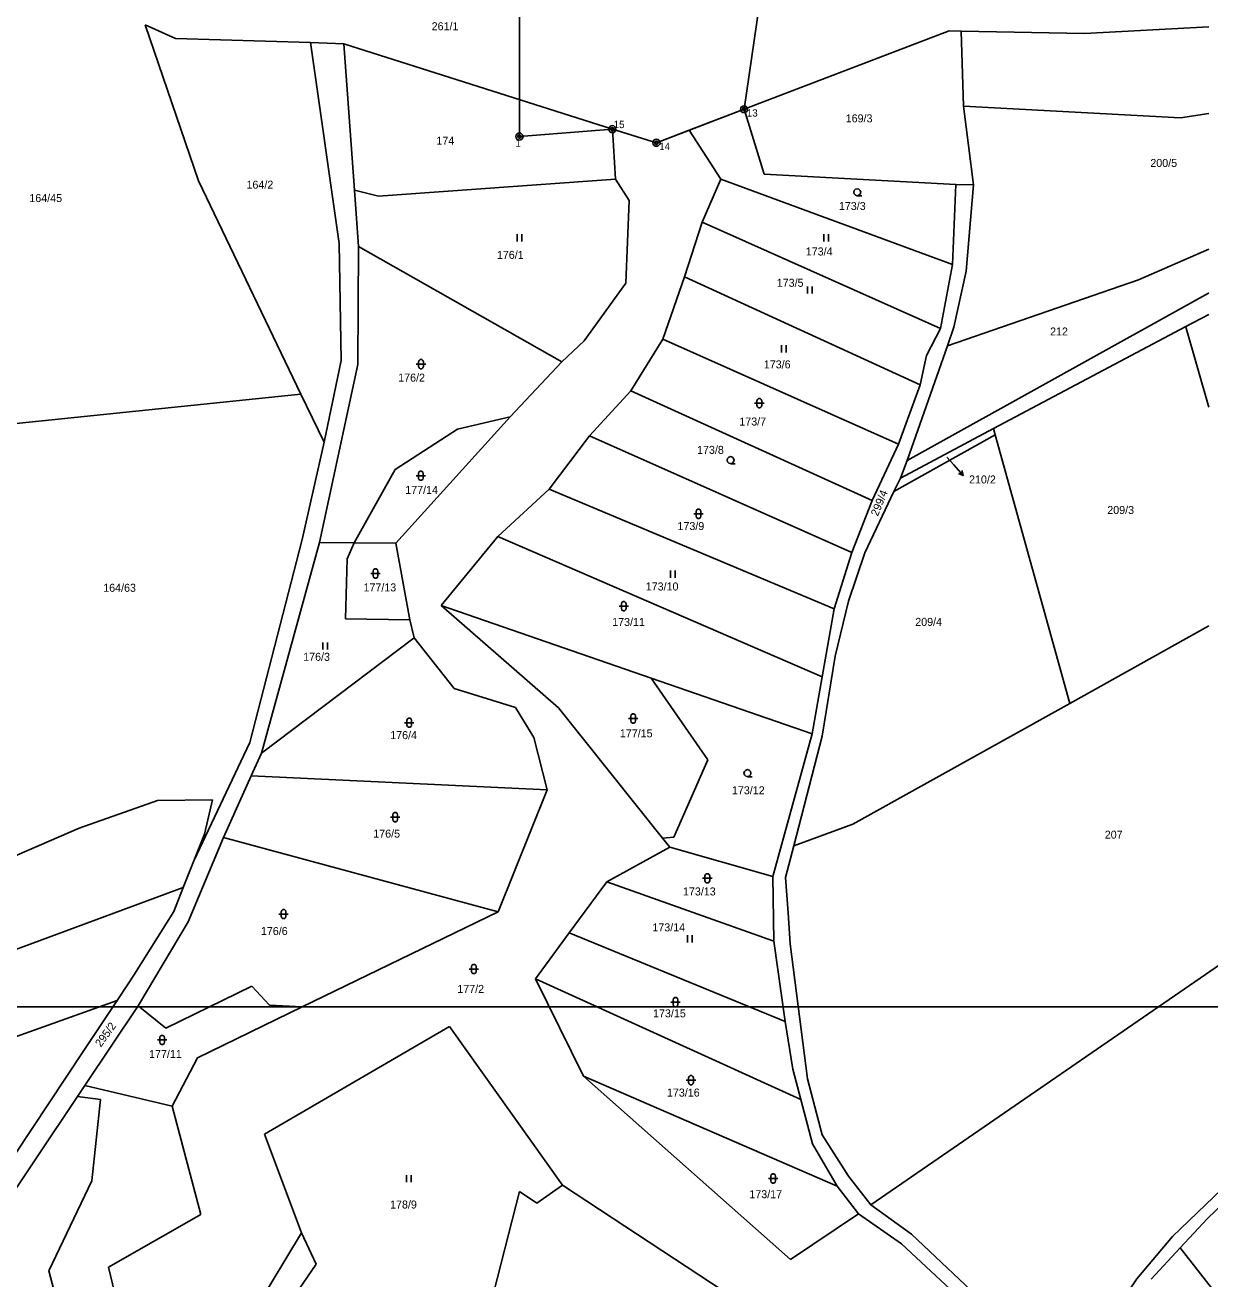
# Model space of a CAD drawing. Extents: x -779723 to -777378, y -1011169 to -1009297.
# Drawn here: x -779360.2 to -779108.5, y -1010745.7 to -1010479.3 of the extents above; entities that cross this region are included whole.
import ezdxf

# ---------------------------------------------------------------- set-up
doc = ezdxf.new("R2010")
doc.units = 0
for name, color, linetype in [('body', 7, 'Continuous'), ('cisla', 7, 'Continuous'), ('Default', 7, 'Continuous'), ('KN_HRANICE', 7, 'Continuous'), ('KN_KULTURY', 7, 'Continuous'), ('KN_PARCELY', 7, 'Continuous'), ('LEGENDA', 7, 'Continuous'), ('obvod_stavby', 7, 'Continuous')]:
    doc.layers.add(name, color=color, linetype=linetype)

# ---------------------------------------------------------------- blocks, each defined once
blk = doc.blocks.new('304')
at = {"layer": 'Default'}
blk.add_lwpolyline([(0, 0), (-0.38, 0.1), (-0.65, 0.37), (-0.75, 0.74), (-0.65, 1.11), (-0.38, 1.38), (-0.01, 1.48), (0.36, 1.38), (0.63, 1.11), (0.73, 0.73), (0.63, 0.35), (0.36, 0.08), (-0.02, -0.02), (0.98, -0.02)], dxfattribs=at)
blk = doc.blocks.new('306')
at = {"layer": 'Default'}
for p, q in [((-0.5, 1.5), (-0.5, 0)), ((0.5, 0), (0.5, 1.5))]:
    blk.add_line(p, q, dxfattribs=at)
blk = doc.blocks.new('316')
at = {"layer": 'Default'}
for points in [[(-1, 1), (0.27, 1), (1, 1)], [(-0.5, 1.5), (-0.4, 1.79), (-0.15, 1.97), (0.16, 1.97), (0.41, 1.79), (0.51, 1.5), (0.51, 0.5), (0.41, 0.21), (0.16, 0.03), (-0.15, 0.03), (-0.4, 0.21), (-0.5, 0.5), (-0.5, 1.5)]]:
    blk.add_lwpolyline(points, dxfattribs=at)
blk = doc.blocks.new('10292')
at = {"layer": 'Default'}
blk.add_line((0, 3), (0, 0), dxfattribs=at)
blk.add_lwpolyline([(-0.5, 2), (0, 3), (0.5, 2)], dxfattribs=at)

msp = doc.modelspace()

# ---------------------------------------------------------------- linework, layer by layer
at = {"layer": 'body'}
for p, q in [((-779207.48, -1010497.19), (-779207.48, -1010497.19)), ((-779235.46, -1010501.42), (-779235.46, -1010501.42)), ((-779255.21, -1010502.98), (-779255.21, -1010502.98)), ((-779226.1, -1010504.31), (-779226.1, -1010504.31))]:
    msp.add_line(p, q, dxfattribs=at)
for centre, radius in [((-779207.48, -1010497.19), 0.75), ((-779207.48, -1010497.19), 0.35), ((-779255.21, -1010502.98), 0.75), ((-779255.21, -1010502.98), 0.35), ((-779235.46, -1010501.42), 0.75), ((-779235.46, -1010501.42), 0.35), ((-779226.1, -1010504.31), 0.75), ((-779226.1, -1010504.31), 0.35)]:
    msp.add_circle(centre, radius, dxfattribs=at)
at = {"layer": 'KN_HRANICE'}
for p, q in [((-779334.72, -1010479.27), (-779323.42, -1010512.4)), ((-779334.72, -1010479.27), (-779328.3, -1010482.13)), ((-779207.48, -1010497.19), (-779163.89, -1010480.52)), ((-779163.89, -1010480.52), (-779161.4, -1010480.57)), ((-779161.4, -1010480.57), (-779160.87, -1010496.55)), ((-779161.4, -1010480.57), (-779135.21, -1010481.09)), ((-779135.21, -1010481.09), (-779108.78, -1010479.68)), ((-779299.61, -1010483.03), (-779328.3, -1010482.13)), ((-779292.52, -1010483.32), (-779299.61, -1010483.03)), ((-779299.61, -1010483.03), (-779293.5, -1010525.69)), ((-779292.52, -1010483.32), (-779290.27, -1010514.35)), ((-779292.52, -1010483.32), (-779235.46, -1010501.42)), ((-779219.15, -1010501.65), (-779207.48, -1010497.19)), ((-779207.48, -1010497.19), (-779203.19, -1010510.98)), ((-779160.87, -1010496.55), (-779158.79, -1010513.22)), ((-779160.87, -1010496.55), (-779114.77, -1010499.04)), ((-779114.77, -1010499.04), (-779108.78, -1010498.11)), ((-779235.46, -1010501.42), (-779234.79, -1010512.03)), ((-779235.46, -1010501.42), (-779226.1, -1010504.31)), ((-779226.1, -1010504.31), (-779219.15, -1010501.65)), ((-779212.41, -1010512.04), (-779219.15, -1010501.65)), ((-779301.63, -1010557.72), (-779323.42, -1010512.4)), ((-779234.79, -1010512.03), (-779285.14, -1010515.63)), ((-779234.79, -1010512.03), (-779231.92, -1010516.57)), ((-779212.41, -1010512.04), (-779216.37, -1010521.17)), ((-779212.41, -1010512.04), (-779163.24, -1010530.16)), ((-779203.19, -1010510.98), (-779162.49, -1010513.2)), ((-779162.49, -1010513.2), (-779163.24, -1010530.16)), ((-779162.49, -1010513.2), (-779158.79, -1010513.22)), ((-779158.79, -1010513.22), (-779160.29, -1010531.61)), ((-779290.27, -1010514.35), (-779285.14, -1010515.63)), ((-779290.27, -1010514.35), (-779289.37, -1010526.33)), ((-779231.92, -1010516.57), (-779232.59, -1010534.14)), ((-779216.37, -1010521.17), (-779220.16, -1010532.8)), ((-779216.37, -1010521.17), (-779165.77, -1010543.76)), ((-779293.5, -1010525.69), (-779293.08, -1010550.56)), ((-779289.37, -1010526.33), (-779289.53, -1010551.4)), ((-779246.22, -1010550.88), (-779289.37, -1010526.33)), ((-779123.71, -1010533.43), (-779108.78, -1010526.89)), ((-779163.24, -1010530.16), (-779165.77, -1010543.76)), ((-779160.29, -1010531.61), (-779162.91, -1010543.51)), ((-779232.59, -1010534.14), (-779241.43, -1010546.37)), ((-779220.16, -1010532.8), (-779224.72, -1010546.03)), ((-779220.16, -1010532.8), (-779170.1, -1010555.73)), ((-779164.3, -1010547.48), (-779123.71, -1010533.43)), ((-779108.83, -1010536.25), (-779172.82, -1010571.78)), ((-779108.78, -1010536.22), (-779108.83, -1010536.25)), ((-779113.68, -1010543.36), (-779108.78, -1010540.76)), ((-779165.77, -1010543.76), (-779168.72, -1010549.53)), ((-779162.91, -1010543.51), (-779164.3, -1010547.48)), ((-779154.51, -1010565.04), (-779113.68, -1010543.36)), ((-779113.58, -1010543.69), (-779113.68, -1010543.36)), ((-779108.78, -1010560.46), (-779113.58, -1010543.69)), ((-779246.22, -1010550.88), (-779241.43, -1010546.37)), ((-779224.72, -1010546.03), (-779231.57, -1010557.02)), ((-779224.72, -1010546.03), (-779174.68, -1010568.37)), ((-779164.3, -1010547.48), (-779172.82, -1010571.78)), ((-779293.08, -1010550.56), (-779296.69, -1010567.88)), ((-779168.72, -1010549.53), (-779170.1, -1010555.73)), ((-779289.53, -1010551.4), (-779297.68, -1010589.2)), ((-779257.2, -1010562.56), (-779246.22, -1010550.88)), ((-779170.1, -1010555.73), (-779174.68, -1010568.37)), ((-779389.01, -1010566.7), (-779301.63, -1010557.72)), ((-779296.69, -1010567.88), (-779301.63, -1010557.72)), ((-779231.57, -1010557.02), (-779240.34, -1010566.54)), ((-779231.57, -1010557.02), (-779180.29, -1010580.29)), ((-779281.44, -1010589.38), (-779257.2, -1010562.56)), ((-779268.35, -1010565.14), (-779257.2, -1010562.56)), ((-779281.62, -1010573.71), (-779268.35, -1010565.14)), ((-779240.34, -1010566.54), (-779248.92, -1010577.89)), ((-779240.34, -1010566.54), (-779184.61, -1010591.38)), ((-779154.14, -1010566.37), (-779175.66, -1010578.41)), ((-779174.28, -1010575.54), (-779154.51, -1010565.04)), ((-779154.14, -1010566.37), (-779154.51, -1010565.04)), ((-779138.26, -1010623.45), (-779154.14, -1010566.37)), ((-779296.69, -1010567.88), (-779301.39, -1010588.58)), ((-779174.68, -1010568.37), (-779180.29, -1010580.29)), ((-779172.82, -1010571.78), (-779174.28, -1010575.54)), ((-779290.32, -1010589.28), (-779281.62, -1010573.71)), ((-779174.28, -1010575.54), (-779175.66, -1010578.41)), ((-779248.92, -1010577.89), (-779259.78, -1010587.95)), ((-779248.92, -1010577.89), (-779188.38, -1010603.3)), ((-779175.66, -1010578.41), (-779181.87, -1010591.44)), ((-779180.29, -1010580.29), (-779184.61, -1010591.38)), ((-779301.39, -1010588.58), (-779312.45, -1010631.73)), ((-779297.68, -1010589.2), (-779309.99, -1010633.95)), ((-779297.68, -1010589.2), (-779290.32, -1010589.28)), ((-779290.32, -1010589.28), (-779291.78, -1010592.73)), ((-779290.32, -1010589.28), (-779281.44, -1010589.38)), ((-779278.52, -1010605.68), (-779281.44, -1010589.38)), ((-779259.78, -1010587.95), (-779271.83, -1010602.61)), ((-779259.78, -1010587.95), (-779190.92, -1010617.79)), ((-779291.78, -1010592.73), (-779292.14, -1010605.43)), ((-779184.61, -1010591.38), (-779188.38, -1010603.3)), ((-779181.87, -1010591.44), (-779185.31, -1010601.66)), ((-779271.83, -1010602.61), (-779227.24, -1010618.06)), ((-779271.83, -1010602.61), (-779246.88, -1010624.34)), ((-779188.38, -1010603.3), (-779190.92, -1010617.79)), ((-779188.16, -1010613.35), (-779185.31, -1010601.66)), ((-779292.14, -1010605.43), (-779278.52, -1010605.68)), ((-779278.52, -1010605.68), (-779277.57, -1010609.48)), ((-779138.26, -1010623.45), (-779108.78, -1010606.95)), ((-779277.57, -1010609.48), (-779309.99, -1010633.95)), ((-779277.57, -1010609.48), (-779269.08, -1010620.21)), ((-779190.89, -1010630.38), (-779188.16, -1010613.35)), ((-779227.24, -1010618.06), (-779193.05, -1010629.9)), ((-779227.24, -1010618.06), (-779215.17, -1010635.42)), ((-779190.92, -1010617.79), (-779193.05, -1010629.9)), ((-779269.08, -1010620.21), (-779256.08, -1010624.31)), ((-779256.08, -1010624.31), (-779252.16, -1010630.69)), ((-779246.88, -1010624.34), (-779224.81, -1010652.01)), ((-779184.36, -1010649.06), (-779138.26, -1010623.45)), ((-779193.05, -1010629.9), (-779201.41, -1010660.18)), ((-779196.91, -1010653.64), (-779190.89, -1010630.38)), ((-779312.45, -1010631.73), (-779324.36, -1010656.85)), ((-779252.16, -1010630.69), (-779249.32, -1010641.76)), ((-779309.99, -1010633.95), (-779312.17, -1010638.8)), ((-779215.17, -1010635.42), (-779222.4, -1010651.81)), ((-779312.17, -1010638.8), (-779318.06, -1010651.91)), ((-779312.17, -1010638.8), (-779249.32, -1010641.76)), ((-779249.32, -1010641.76), (-779259.7, -1010667.71)), ((-779348.77, -1010649.95), (-779332.07, -1010644.04)), ((-779332.07, -1010644.04), (-779320.39, -1010643.9)), ((-779320.39, -1010643.9), (-779322.12, -1010651.21)), ((-779196.91, -1010653.64), (-779184.36, -1010649.06)), ((-779368.68, -1010658.56), (-779348.77, -1010649.95)), ((-779322.12, -1010651.21), (-779324.36, -1010656.85)), ((-779222.4, -1010651.81), (-779224.81, -1010652.01)), ((-779318.06, -1010651.91), (-779325.55, -1010669.8)), ((-779318.06, -1010651.91), (-779259.7, -1010667.71)), ((-779236.67, -1010661.34), (-779223.26, -1010653.93)), ((-779224.81, -1010652.01), (-779223.26, -1010653.93)), ((-779223.26, -1010653.93), (-779201.41, -1010660.18)), ((-779198.66, -1010660.39), (-779196.91, -1010653.64)), ((-779326.62, -1010662.54), (-779324.36, -1010656.85)), ((-779236.67, -1010661.34), (-779244.63, -1010672.17)), ((-779236.67, -1010661.34), (-779201.2, -1010673.91)), ((-779201.41, -1010660.18), (-779201.2, -1010673.91)), ((-779198.15, -1010667.92), (-779198.66, -1010660.39)), ((-779326.62, -1010662.54), (-779412.71, -1010694.4)), ((-779328.65, -1010667.63), (-779326.62, -1010662.54)), ((-779337.14, -1010681.17), (-779328.65, -1010667.63)), ((-779259.7, -1010667.71), (-779301.35, -1010687.91)), ((-779325.55, -1010669.8), (-779336.2, -1010687.64)), ((-779197.71, -1010674.51), (-779198.15, -1010667.92)), ((-779244.63, -1010672.17), (-779251.78, -1010681.91)), ((-779244.63, -1010672.17), (-779198.79, -1010690.97)), ((-779201.2, -1010673.91), (-779198.79, -1010690.97)), ((-779194.02, -1010703.17), (-779197.71, -1010674.51)), ((-779338.32, -1010683.01), (-779337.14, -1010681.17)), ((-779180.57, -1010729.93), (-779106.25, -1010678.83)), ((-779340.67, -1010686.56), (-779338.32, -1010683.01)), ((-779330.33, -1010692.44), (-779312.04, -1010683.48)), ((-779312.04, -1010683.48), (-779308.33, -1010687.51)), ((-779251.78, -1010681.91), (-779195.42, -1010707.58)), ((-779251.78, -1010681.91), (-779241.63, -1010702.58)), ((-779340.67, -1010686.56), (-779413.52, -1010712.43)), ((-779347.72, -1010697.18), (-779340.67, -1010686.56)), ((-779336.2, -1010687.64), (-779347.52, -1010704.57)), ((-779336.2, -1010687.64), (-779330.33, -1010692.44)), ((-779301.35, -1010687.91), (-779323.61, -1010698.7)), ((-779308.33, -1010687.51), (-779301.35, -1010687.91)), ((-779198.79, -1010690.97), (-779197.12, -1010701.12)), ((-779309.36, -1010714.92), (-779270.06, -1010692.04)), ((-779270.06, -1010692.04), (-779246.07, -1010725.76)), ((-779367.53, -1010726.93), (-779347.72, -1010697.18)), ((-779329.01, -1010708.95), (-779323.61, -1010698.7)), ((-779197.12, -1010701.12), (-779195.42, -1010707.58)), ((-779347.52, -1010704.57), (-779349.1, -1010706.93)), ((-779347.52, -1010704.57), (-779329.01, -1010708.95)), ((-779197.61, -1010741.55), (-779241.63, -1010702.58)), ((-779241.63, -1010702.58), (-779187.71, -1010725.99)), ((-779190.93, -1010715.06), (-779194.02, -1010703.17)), ((-779349.1, -1010706.93), (-779367.48, -1010734.41)), ((-779349.1, -1010706.93), (-779344.18, -1010707.57)), ((-779344.18, -1010707.57), (-779346.07, -1010724.81)), ((-779195.42, -1010707.58), (-779192.95, -1010716.95)), ((-779329.01, -1010708.95), (-779322.87, -1010731.97)), ((-779309.36, -1010714.92), (-779301.54, -1010735.91)), ((-779185.34, -1010723.85), (-779190.93, -1010715.06)), ((-779192.95, -1010716.95), (-779187.71, -1010725.99)), ((-779095.53, -1010716.56), (-779116.46, -1010736.64)), ((-779109.06, -1010732.81), (-779096.96, -1010721.21)), ((-779346.07, -1010724.81), (-779355.18, -1010743.98)), ((-779251.52, -1010729.6), (-779246.07, -1010725.76)), ((-779246.07, -1010725.76), (-779197.77, -1010757.47)), ((-779187.71, -1010725.99), (-779183.15, -1010731.82)), ((-779180.57, -1010729.93), (-779185.34, -1010723.85)), ((-779255.21, -1010727.12), (-779263.87, -1010760.8)), ((-779255.21, -1010727.12), (-779251.52, -1010729.6)), ((-779171.89, -1010736.2), (-779180.57, -1010729.93)), ((-779322.87, -1010731.97), (-779342.51, -1010743.15)), ((-779197.61, -1010741.55), (-779183.15, -1010731.82)), ((-779183.15, -1010731.82), (-779174.03, -1010738.22)), ((-779114.85, -1010739.08), (-779109.06, -1010732.81)), ((-779312.63, -1010754.3), (-779301.54, -1010735.91)), ((-779301.54, -1010735.91), (-779298.42, -1010742.54)), ((-779138.78, -1010767.46), (-779171.89, -1010736.2)), ((-779116.46, -1010736.64), (-779124.03, -1010745.63)), ((-779174.03, -1010738.22), (-779140.28, -1010769.67)), ((-779121, -1010745.73), (-779114.85, -1010739.08)), ((-779114.85, -1010739.08), (-779044.24, -1010829.34)), ((-779355.18, -1010743.98), (-779347.99, -1010770.65)), ((-779342.51, -1010743.15), (-779336.5, -1010768.5)), ((-779306.77, -1010754.81), (-779298.42, -1010742.54)), ((-779138.78, -1010767.46), (-779124.03, -1010745.63))]:
    msp.add_line(p, q, dxfattribs=at)
at = {"layer": 'KN_PARCELY'}
msp.add_line((-779164.4, -1010571.13), (-779162.94, -1010572.75), dxfattribs=at)
at = {"layer": 'LEGENDA'}
msp.add_lwpolyline([(-779530.66, -1010687.91), (-778936.66, -1010687.91), (-778936.66, -1010267.91), (-779530.66, -1010267.91)], close=True, dxfattribs=at)
at = {"layer": 'obvod_stavby'}
msp.add_lwpolyline([(-779249.69, -1010446.5), (-779249.69, -1010426.74), (-779238.66, -1010426.74), (-779242.1, -1010401.61), (-779239.48, -1010394.92), (-779235.13, -1010426.74), (-779233.15, -1010426.74), (-779223.61, -1010445.86), (-779200.73, -1010455.74), (-779202.13, -1010460.62), (-779207.48, -1010497.19), (-779226.1, -1010504.31), (-779235.46, -1010501.42), (-779255.21, -1010502.98), (-779255.18, -1010446.63), (-779249.69, -1010446.5)], dxfattribs=at)

# ---------------------------------------------------------------- block references
at = {"layer": 'KN_KULTURY'}
for name, p in [('304', (-779183.45, -1010515.55)), ('306', (-779255.22, -1010525.25)), ('306', (-779190.04, -1010525.25)), ('306', (-779193.5, -1010536.35)), ('306', (-779199.05, -1010548.83)), ('316', (-779276.13, -1010552.33)), ('316', (-779204.25, -1010560.63)), ('304', (-779210.34, -1010572.46)), ('316', (-779276.15, -1010576.04)), ('316', (-779217.18, -1010584.14)), ('316', (-779285.79, -1010596.82)), ('306', (-779222.63, -1010596.7)), ('316', (-779233.06, -1010603.75)), ('306', (-779296.48, -1010611.97)), ('316', (-779278.62, -1010628.51)), ('316', (-779231.05, -1010627.61)), ('304', (-779206.77, -1010638.96)), ('316', (-779281.63, -1010648.57)), ('316', (-779215.3, -1010661.57)), ('316', (-779305.31, -1010669.17)), ('306', (-779219.04, -1010674.18)), ('316', (-779264.9, -1010680.84)), ('316', (-779222.05, -1010687.89)), ('316', (-779331.1, -1010695.9)), ('316', (-779218.77, -1010704.46)), ('306', (-779278.73, -1010725.12)), ('316', (-779201.31, -1010725.34))]:
    msp.add_blockref(name, p, dxfattribs=at)
at = {"layer": 'KN_PARCELY', "rotation": -138.03614999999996}
msp.add_blockref('10292', (-779162.94, -1010572.75), dxfattribs=at)

# ---------------------------------------------------------------- texts
at = {"layer": 'cisla'}
for s, p in [(' 13', (-779207.48, -1010498.74)), (' 15', (-779235.77, -1010501.19)), ('  1', (-779257.22, -1010505.15)), (' 14', (-779226.1, -1010505.86))]:
    msp.add_text(s, height=1.552, dxfattribs=at).set_placement(p)
at = {"layer": 'KN_PARCELY'}
for s, height, p in [('261/1', 1.7, (-779273.86, -1010480.4)), ('169/3', 1.7, (-779185.9, -1010499.97)), ('174', 1.7, (-779272.85, -1010504.71)), ('200/5', 1.7, (-779121.19, -1010509.44)), ('164/2', 1.7, (-779313.19, -1010514.06)), ('164/45', 1.7, (-779359.32, -1010516.91)), ('173/3', 1.7, (-779187.35, -1010518.59)), ('173/4', 1.7, (-779194.39, -1010528.25)), ('176/1', 1.7, (-779260, -1010528.98)), ('173/5', 1.7, (-779200.55, -1010534.9)), ('212', 1.7, (-779142.49, -1010545.25)), ('173/6', 1.7, (-779203.3, -1010552.24)), ('176/2', 1.7, (-779280.97, -1010555.05)), ('173/7', 1.7, (-779208.5, -1010564.38)), ('173/8', 1.7, (-779217.48, -1010570.4)), ('210/2', 0.1, (-779164.39, -1010571.13)), ('177/14', 1.7, (-779279.47, -1010578.91)), ('210/2', 1.7, (-779159.7, -1010576.68)), ('209/3', 1.7, (-779130.34, -1010583.17)), ('173/9', 1.7, (-779221.64, -1010586.58)), ('164/63', 1.7, (-779343.63, -1010599.7)), ('177/13', 1.7, (-779288.34, -1010599.62)), ('173/10', 1.7, (-779228.38, -1010599.42)), ('173/11', 1.7, (-779235.51, -1010606.96)), ('209/4', 1.7, (-779171.13, -1010606.94)), ('176/3', 1.7, (-779301.15, -1010614.36)), ('176/4', 1.7, (-779282.66, -1010631)), ('177/15', 1.7, (-779233.88, -1010630.62)), ('173/12', 1.7, (-779210.07, -1010642.72)), ('176/5', 1.7, (-779286.26, -1010651.93)), ('207', 1.7, (-779130.87, -1010652.15)), ('173/13', 1.7, (-779220.47, -1010664.21)), ('173/14', 1.7, (-779226.97, -1010671.84)), ('176/6', 1.7, (-779310.13, -1010672.62)), ('177/2', 1.7, (-779268.41, -1010684.92)), ('173/15', 1.7, (-779226.83, -1010690.11)), ('177/11', 1.7, (-779333.89, -1010698.75)), ('173/16', 1.7, (-779223.88, -1010706.94)), ('178/9', 1.7, (-779282.69, -1010730.72)), ('173/17', 1.7, (-779206.37, -1010728.53))]:
    msp.add_text(s, height=height, dxfattribs=at).set_placement(p)
for s, rotation, p in [('299/4', 67.781, (-779179.08, -1010583.77)), ('295/2', 53.973, (-779344.13, -1010696.55))]:
    msp.add_text(s, height=1.7, rotation=rotation, dxfattribs=at).set_placement(p)

doc.saveas('drawing.dxf')
